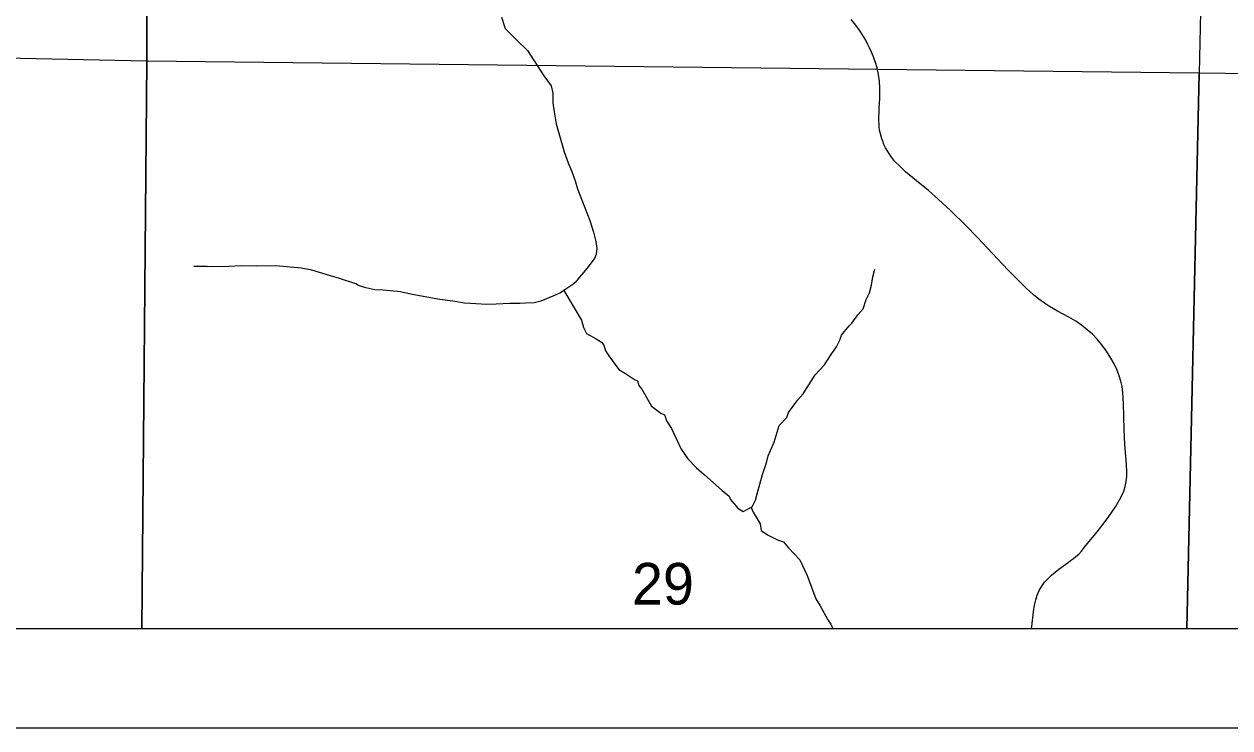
# Model space of a CAD drawing. Extents: x 0 to 34, y 0 to 22.
# Drawn here: x 5.516 to 6.729, y 14 to 14.708 of the extents above; entities that cross this region are included whole.
import ezdxf

# ---------------------------------------------------------------- set-up
doc = ezdxf.new("R2010")
doc.units = 0
for name, color, linetype in [('GM_X_Minor_River', 7, 'Continuous'), ('GM_X_Rail_Line', 7, 'Continuous'), ('GM_X_Section', 7, 'Continuous'), ('GM_X_Section_Text', 7, 'Continuous'), ('GM_X_State_Shield', 7, 'Continuous'), ('GM_X_Township_Road', 7, 'Continuous'), ('SH_Cut_Line', 7, 'Continuous'), ('SH_Data', 7, 'Continuous')]:
    doc.layers.add(name, color=color, linetype=linetype)

msp = doc.modelspace()

# ---------------------------------------------------------------- linework, layer by layer
at = {"layer": 'GM_X_Minor_River'}
for points in [[(5.996, 14.7148), (5.9996, 14.7031), (6.0116, 14.6911), (6.022, 14.681), (6.0387, 14.6558), (6.0461, 14.6457), (6.0478, 14.6381), (6.0478, 14.6343), (6.0476, 14.6286), (6.0489, 14.6195), (6.051, 14.6074), (6.059, 14.5794), (6.063, 14.5681), (6.067, 14.5583), (6.0702, 14.55), (6.0726, 14.542), (6.0758, 14.5333), (6.0802, 14.5224), (6.0849, 14.5103), (6.0885, 14.4986), (6.091, 14.4891), (6.0919, 14.4819), (6.0912, 14.4762), (6.0894, 14.472), (6.0868, 14.4685), (6.0831, 14.4635), (6.0786, 14.4578), (6.0741, 14.4528), (6.0704, 14.4481), (6.0678, 14.4458), (6.0648, 14.4439), (6.0607, 14.4411), (6.0554, 14.4376), (6.0475, 14.4341), (6.0355, 14.429), (6.0287, 14.4273), (6.0203, 14.4272), (6.0146, 14.4267), (6.0044, 14.4266), (5.9907, 14.426), (5.9812, 14.4258), (5.9702, 14.4264), (5.9588, 14.427), (5.947, 14.4291), (5.9341, 14.4308), (5.9097, 14.435), (5.8983, 14.4374), (5.8945, 14.4385), (5.877, 14.4402), (5.8686, 14.4404)], [(5.8686, 14.4404), (5.8595, 14.4425), (5.8522, 14.4447), (5.8495, 14.4466), (5.8331, 14.452), (5.824, 14.4545), (5.8053, 14.4603), (5.7946, 14.4624), (5.7691, 14.4647), (5.749, 14.4643), (5.7342, 14.4645), (5.7217, 14.4639), (5.7038, 14.4636), (5.6997, 14.464), (5.6864, 14.4641)], [(6.0587, 14.4398), (6.0764, 14.4099), (6.0784, 14.4027), (6.0816, 14.3966), (6.0912, 14.3911), (6.0965, 14.3878), (6.0989, 14.3848), (6.1005, 14.3791), (6.104, 14.3742), (6.1141, 14.3603), (6.1206, 14.3562), (6.1298, 14.3503), (6.1329, 14.3488), (6.1341, 14.3443), (6.1372, 14.3405), (6.147, 14.3236), (6.1562, 14.3165), (6.1601, 14.3147), (6.1609, 14.312), (6.1621, 14.3086), (6.1671, 14.3011), (6.1719, 14.2909), (6.1766, 14.2804), (6.1836, 14.2706), (6.1921, 14.2616), (6.2002, 14.2545), (6.2179, 14.2388), (6.2249, 14.2329), (6.2264, 14.2295), (6.2338, 14.2209), (6.2392, 14.2175), (6.2482, 14.2222), (6.2515, 14.2291), (6.2533, 14.2352), (6.2587, 14.2547), (6.2626, 14.2665), (6.2644, 14.2734), (6.2702, 14.2872), (6.2753, 14.3039), (6.2831, 14.312), (6.2849, 14.317), (6.2942, 14.3297), (6.2994, 14.3359), (6.3116, 14.355), (6.3209, 14.3651), (6.3276, 14.3754), (6.3331, 14.3831), (6.3364, 14.39), (6.3382, 14.395), (6.3457, 14.4042), (6.3486, 14.4069), (6.3546, 14.4154), (6.3598, 14.4215), (6.363, 14.4307), (6.3663, 14.4376), (6.3681, 14.4452), (6.3695, 14.4536), (6.3716, 14.4612)], [(6.2473, 14.2217), (6.2491, 14.2169), (6.2561, 14.2052), (6.2573, 14.1984), (6.2635, 14.194), (6.2738, 14.1892), (6.2796, 14.187), (6.2846, 14.181), (6.2962, 14.169), (6.3037, 14.1532), (6.3121, 14.1298), (6.3167, 14.1226), (6.3242, 14.1087), (6.3273, 14.1042), (6.3292, 14.1)]]:
    msp.add_lwpolyline(points, dxfattribs=at)
at = {"layer": 'GM_X_Rail_Line'}
msp.add_lwpolyline([(7.149, 16.6283), (5.9824, 16.6436), (5.6594, 16.6485), (5.6614, 16.7344), (5.6628, 16.7878), (5.6628, 16.7899), (5.6656, 16.9939), (5.6743, 17.6274), (5.3403, 17.635), (5.2052, 17.638), (4.9797, 17.6498), (4.9624, 17.6496), (4.8158, 17.6467), (4.5489, 17.6578), (4.5478, 16.582), (4.5509, 15.5331), (4.5658, 14.9668), (4.5781, 14.1), (8.76, 14.1)], dxfattribs=at)
at = {"layer": 'GM_X_Section'}
for points in [[(4.5625, 15.6671), (5.6397, 15.6496), (5.6391, 14.6704), (4.5729, 14.6928), (4.5655, 15.3289)], [(5.6397, 15.6496), (6.7192, 15.6301), (6.698, 14.6582), (5.6391, 14.6704)]]:
    msp.add_lwpolyline(points, close=True, dxfattribs=at)
at = {"layer": 'GM_X_State_Shield'}
for points in [[(4.5791, 14.1), (5.6342, 14.1), (5.6391, 14.6704), (4.5729, 14.6928), (4.5765, 14.3313)], [(5.6342, 14.1), (6.6856, 14.1), (6.698, 14.6582), (5.6391, 14.6704)], [(6.6856, 14.1), (7.7238, 14.1), (7.7293, 14.6454), (6.698, 14.6582)]]:
    msp.add_lwpolyline(points, close=True, dxfattribs=at)
at = {"layer": 'GM_X_Township_Road'}
for points in [[(6.3795, 14.5899), (6.3785, 14.5924), (6.3772, 14.5972), (6.3763, 14.6009), (6.3759, 14.6045), (6.3757, 14.6132), (6.3759, 14.6199), (6.3761, 14.6236), (6.3763, 14.6279), (6.3766, 14.6328), (6.3767, 14.6384), (6.3767, 14.6434), (6.3763, 14.6502), (6.3754, 14.6569), (6.3739, 14.6636), (6.3724, 14.6689), (6.3717, 14.6707), (6.3703, 14.6748), (6.3684, 14.6794), (6.3664, 14.6839), (6.3647, 14.6872), (6.3624, 14.6916), (6.3601, 14.6953), (6.3568, 14.7005), (6.3524, 14.7065), (6.3477, 14.7122)], [(6.5294, 14.1), (6.5295, 14.102), (6.5312, 14.1167), (6.5323, 14.1235), (6.5336, 14.1289), (6.5351, 14.1336), (6.5371, 14.1381), (6.5395, 14.1424), (6.5424, 14.1464), (6.5452, 14.1496), (6.5492, 14.1534), (6.5566, 14.1595), (6.566, 14.1663), (6.5686, 14.1682), (6.5715, 14.1703), (6.5739, 14.1724), (6.5767, 14.1748), (6.5794, 14.1777), (6.5824, 14.1817), (6.5856, 14.1855), (6.5939, 14.1953), (6.6004, 14.2036), (6.6071, 14.2126), (6.6137, 14.2223), (6.6179, 14.2292), (6.6202, 14.2336), (6.6221, 14.2381), (6.6236, 14.2428), (6.6246, 14.2477), (6.6252, 14.2526), (6.6253, 14.2575), (6.6249, 14.265), (6.6233, 14.2854), (6.6225, 14.2997), (6.6218, 14.3264), (6.6211, 14.3369), (6.6203, 14.3431), (6.6192, 14.3486), (6.6176, 14.3539), (6.6154, 14.3597), (6.6125, 14.3659), (6.6092, 14.3719), (6.6048, 14.3787), (6.6, 14.3852), (6.5953, 14.3909), (6.5905, 14.3958), (6.5854, 14.4004), (6.5795, 14.405), (6.5739, 14.4088), (6.5669, 14.4129), (6.5555, 14.4191), (6.5474, 14.4237), (6.5422, 14.427), (6.5367, 14.431), (6.5314, 14.4353), (6.524, 14.442), (6.5152, 14.4507), (6.5113, 14.4547), (6.5091, 14.4569), (6.5056, 14.4604), (6.4949, 14.4717), (6.4749, 14.493), (6.4632, 14.505), (6.4477, 14.5202), (6.4354, 14.5317), (6.4256, 14.5402), (6.4137, 14.5502), (6.4026, 14.5592), (6.3967, 14.5647), (6.3919, 14.5696), (6.3884, 14.5738), (6.3852, 14.5784), (6.3824, 14.5832), (6.3807, 14.5866), (6.3795, 14.5899)]]:
    msp.add_lwpolyline(points, dxfattribs=at)
at = {"layer": 'SH_Cut_Line'}
msp.add_lwpolyline([(7.149, 16.6283), (5.9824, 16.6436), (5.6594, 16.6485), (5.6614, 16.7344), (5.6628, 16.7878), (5.6628, 16.7899), (5.6656, 16.9939), (5.6743, 17.6274), (5.3403, 17.635), (5.2052, 17.638), (4.9797, 17.6498), (4.9624, 17.6496), (4.8158, 17.6467), (4.5489, 17.6578), (4.5478, 16.582), (4.5509, 15.5331), (4.5658, 14.9668), (4.5781, 14.1), (8.9, 14.1)], dxfattribs=at)
at = {"layer": 'SH_Data'}
for p, q in [((2.1, 14.1), (8.9, 14.1)), ((2, 14), (9, 14))]:
    msp.add_line(p, q, dxfattribs=at)

# ---------------------------------------------------------------- texts
at = {"layer": 'GM_X_Section_Text'}
msp.add_text('29', height=0.04186, rotation=0, dxfattribs=at).set_placement((6.1273, 14.124))

doc.saveas('drawing.dxf')
